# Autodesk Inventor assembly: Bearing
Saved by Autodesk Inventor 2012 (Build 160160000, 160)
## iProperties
Created: 2011-12
Part Number: Bearing
Document SubType Name: Assembly
Designer: Admin
ClientObjectVersion: 1
Author: Admin
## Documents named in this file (2)
- C:\CMU\Datasets\Session 6\Cluster Ex 1\Workspaces\Workspace\GearBox-A\Design Accelerator\Bearing4.iam
- C:\CMU\Datasets\Session 6\Cluster Ex 1\Libraries\Content Center Files\en-US\DIN 618 - T1  HK\DIN 618 - HK3020 - 30 x 37 x 20.ipt
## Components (1 placed, 1 different names)
1. DIN 618 - T1 HK HK3020 - 30 x 37 x 20:1
